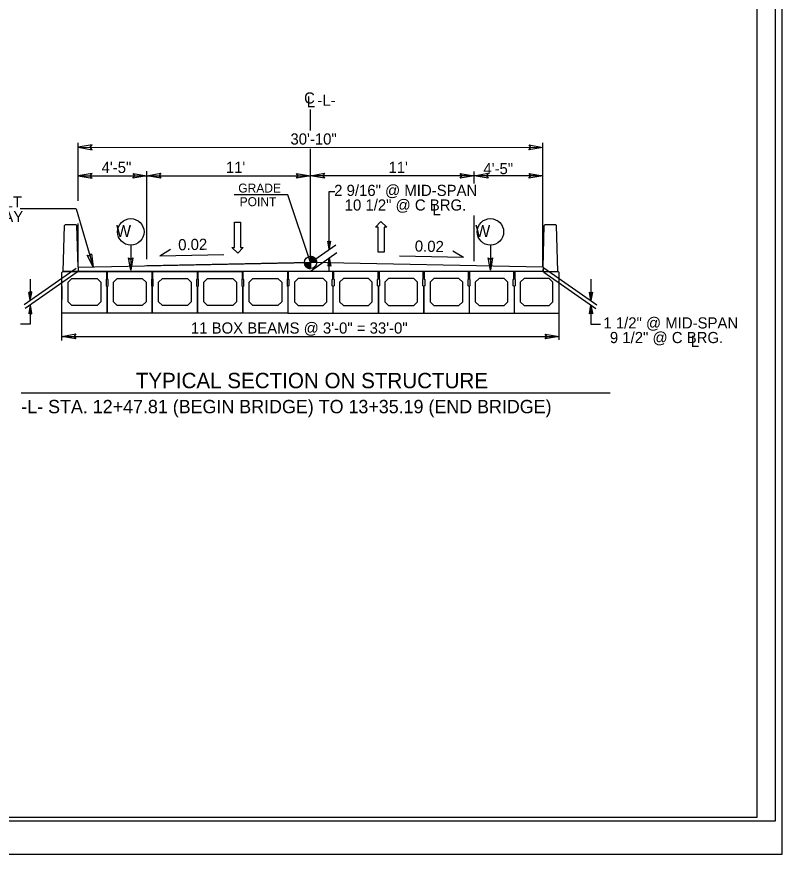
# Model space of a CAD drawing. Extents: x 573711 to 575883, y -54585 to -53485.
# Drawn here: x 574880 to 575395, y -54585 to -54021 of the extents above; entities that cross this region are included whole.
import ezdxf

# ---------------------------------------------------------------- set-up
doc = ezdxf.new("R2010")
doc.units = 0
for name, color, linetype in [('Old_Level_1', 7, 'Continuous'), ('Old_Level_11', 7, 'Continuous'), ('Old_Level_2', 7, 'Continuous'), ('Old_Level_20', 7, 'Continuous'), ('Old_Level_3', 7, 'Continuous'), ('Prop Dimension Text', 7, 'Continuous'), ('Prop Lane Arrow CELL', 7, 'Continuous'), ('Prop Terminator CELL', 7, 'Continuous'), ('Sheet Cutting Line CELL', 7, 'Continuous'), ('Sheet Plot Border Inside CELL', 7, 'Continuous'), ('Sheet Plot Border Outside CELL', 7, 'Continuous'), ('Sheet Typical CELL', 7, 'Continuous'), ('Typical Bridge Rail CELL', 7, 'Continuous'), ('Typical Terminator CELL', 7, 'Continuous')]:
    doc.layers.add(name, color=color, linetype=linetype)

msp = doc.modelspace()

# ---------------------------------------------------------------- linework, layer by layer
at = {"layer": 'Old_Level_1'}
for p, q in [((575077.4, -54097.63), (575077.41, -54083.4)), ((575077.4, -54186.4), (575077.4, -54109.84)), ((575090.02, -54177.56), (575090.02, -54138.73)), ((575090.02, -54138.73), (575093.85, -54138.73)), ((575077.4, -54186.4), (575094.41, -54174.48)), ((575090.02, -54177.56), (575089.05, -54172.03)), ((575089.05, -54172.03), (575090.02, -54172.75)), ((575089.19, -54172.14), (575090.02, -54177.56)), ((575090.02, -54177.56), (575089.32, -54172.24)), ((575089.46, -54172.35), (575090.02, -54177.56)), ((575090.02, -54177.56), (575089.6, -54172.44)), ((575089.74, -54172.54), (575090.02, -54177.56)), ((575090.02, -54177.56), (575089.88, -54172.64)), ((575090.02, -54177.56), (575091, -54172.03)), ((575090.02, -54172.75), (575091, -54172.03)), ((575090.02, -54177.56), (575090.85, -54172.14)), ((575090.71, -54172.24), (575090.02, -54177.56)), ((575090.02, -54177.56), (575090.57, -54172.35)), ((575090.44, -54172.44), (575090.02, -54177.56)), ((575090.02, -54177.56), (575090.3, -54172.54)), ((575090.16, -54172.64), (575090.02, -54177.56)), ((575090.02, -54172.75), (575090.02, -54177.56)), ((575077.39, -54192.18), (575095.11, -54179.77)), ((574920.85, -54189.55), (575077.4, -54186.4)), ((575077.4, -54186.4), (574967.2, -54188.62)), ((575073.25, -54186.4), (575077.4, -54186.4)), ((575077.39, -54190.55), (575077.4, -54186.4)), ((575077.4, -54186.4), (575077.39, -54190.55)), ((575077.4, -54186.4), (575077.4, -54182.25)), ((575233.96, -54189.55), (575077.4, -54186.4)), ((575081.54, -54186.4), (575077.4, -54186.4)), ((575090.02, -54183.34), (575089.05, -54188.86)), ((575090.02, -54183.34), (575089.19, -54188.76)), ((575089.33, -54188.65), (575090.02, -54183.34)), ((575090.02, -54183.34), (575089.46, -54188.55)), ((575089.6, -54188.45), (575090.02, -54183.34)), ((575090.02, -54183.34), (575089.74, -54188.35)), ((575089.88, -54188.25), (575090.02, -54183.34)), ((575090.02, -54183.34), (575091, -54188.86)), ((575090.85, -54188.76), (575090.02, -54183.34)), ((575090.02, -54183.34), (575090.71, -54188.65)), ((575090.58, -54188.55), (575090.02, -54183.34)), ((575090.02, -54183.34), (575090.44, -54188.45)), ((575090.3, -54188.35), (575090.02, -54183.34)), ((575090.02, -54183.34), (575090.16, -54188.25)), ((575090.02, -54188.14), (575090.02, -54183.34)), ((575090.02, -54192.62), (575090.02, -54183.34)), ((574919.63, -54190.4), (574884.61, -54214.93)), ((575090.02, -54188.14), (575089.05, -54188.86)), ((575091, -54188.86), (575090.02, -54188.14)), ((575234.59, -54189.97), (575270.23, -54214.94)), ((574920.25, -54192.97), (574885.21, -54217.51)), ((574888.59, -54197.7), (574888.59, -54212.13)), ((574920.94, -54192.56), (574910.79, -54192.56)), ((575233.99, -54192.56), (574920.84, -54192.56)), ((575233.89, -54192.56), (575244.26, -54192.56)), ((575234.58, -54192.98), (575269.63, -54217.52)), ((575266.24, -54197.7), (575266.24, -54212.14)), ((574888.59, -54212.13), (574887.62, -54206.61)), ((574887.62, -54206.61), (574888.59, -54207.33)), ((574887.76, -54206.71), (574888.59, -54212.13)), ((574888.59, -54212.13), (574889.57, -54206.61)), ((574888.59, -54207.33), (574889.57, -54206.61)), ((574888.59, -54212.13), (574888.87, -54207.12)), ((575266.24, -54212.14), (575265.27, -54206.61)), ((575266.24, -54207.33), (575265.27, -54206.61)), ((575266.24, -54212.14), (575265.96, -54207.12)), ((575266.24, -54212.14), (575267.22, -54206.61)), ((575267.22, -54206.61), (575266.24, -54207.33)), ((575267.07, -54206.71), (575266.24, -54212.14)), ((574888.59, -54215.15), (574887.61, -54220.68)), ((574888.59, -54219.96), (574887.61, -54220.68)), ((574888.59, -54215.15), (574888.59, -54228.07)), ((574888.59, -54215.15), (574889.56, -54220.68)), ((574889.56, -54220.68), (574888.59, -54219.96)), ((575266.25, -54215.15), (575265.27, -54220.68)), ((575265.27, -54220.68), (575266.25, -54219.96)), ((575266.25, -54215.15), (575266.25, -54228.07)), ((575266.25, -54215.15), (575267.22, -54220.68)), ((575266.25, -54219.96), (575267.22, -54220.68)), ((574888.59, -54228.07), (574882.15, -54228.07)), ((575266.25, -54228.07), (575272.68, -54228.07))]:
    msp.add_line(p, q, dxfattribs=at)
for points in [[(575073.27, -54186.4), (575073.27, -54186.85)], [(575073.35, -54186.4), (575073.35, -54187.34)], [(575073.43, -54186.4), (575073.43, -54187.64)], [(575073.51, -54186.4), (575073.51, -54187.89)], [(575073.6, -54186.4), (575073.6, -54188.08)], [(575073.68, -54186.4), (575073.68, -54188.25)], [(575073.76, -54186.4), (575073.76, -54188.41)], [(575073.85, -54186.4), (575073.85, -54188.56)], [(575073.93, -54186.4), (575073.93, -54188.69)], [(575074.01, -54186.4), (575074.01, -54188.81)], [(575074.1, -54186.4), (575074.1, -54188.92)], [(575074.18, -54186.4), (575074.18, -54189.02)], [(575074.26, -54186.4), (575074.26, -54189.12)], [(575074.34, -54186.4), (575074.34, -54189.21)], [(575074.43, -54186.4), (575074.43, -54189.3)], [(575074.51, -54186.4), (575074.51, -54189.39)], [(575074.59, -54186.4), (575074.59, -54189.46)], [(575074.68, -54186.4), (575074.68, -54189.54)], [(575074.76, -54186.4), (575074.76, -54189.61)], [(575074.84, -54186.4), (575074.84, -54189.67)], [(575074.93, -54186.4), (575074.93, -54189.74)], [(575075.01, -54186.4), (575075.01, -54189.79)], [(575075.09, -54186.4), (575075.09, -54189.85)], [(575075.17, -54186.4), (575075.17, -54189.9)], [(575075.26, -54186.4), (575075.26, -54189.96)], [(575075.34, -54186.4), (575075.34, -54190.01)], [(575075.42, -54186.4), (575075.42, -54190.05)], [(575075.51, -54186.4), (575075.51, -54190.1)], [(575075.59, -54186.4), (575075.59, -54190.13)], [(575075.67, -54186.4), (575075.67, -54190.17)], [(575075.76, -54186.4), (575075.76, -54190.21)], [(575075.84, -54186.4), (575075.84, -54190.25)], [(575075.92, -54186.4), (575075.92, -54190.28)], [(575076, -54186.4), (575076, -54190.31)], [(575076.09, -54186.4), (575076.09, -54190.34)], [(575076.17, -54186.4), (575076.17, -54190.36)], [(575076.25, -54186.4), (575076.25, -54190.38)], [(575076.34, -54186.4), (575076.34, -54190.41)], [(575076.42, -54186.4), (575076.42, -54190.43)], [(575076.5, -54186.4), (575076.5, -54190.45)], [(575076.58, -54186.4), (575076.58, -54190.47)], [(575076.67, -54186.4), (575076.67, -54190.49)], [(575076.75, -54186.4), (575076.75, -54190.49)], [(575076.83, -54186.4), (575076.83, -54190.51)], [(575076.92, -54186.4), (575076.92, -54190.52)], [(575077, -54186.4), (575077, -54190.53)], [(575077.08, -54186.4), (575077.08, -54190.54)], [(575077.17, -54186.4), (575077.16, -54190.54)], [(575077.25, -54186.4), (575077.25, -54190.55)], [(575077.33, -54186.4), (575077.33, -54190.55), (575077.33, -54190.55)], [(575077.43, -54182.25), (575077.43, -54182.25), (575077.43, -54186.4)], [(575077.52, -54182.25), (575077.52, -54186.4)], [(575077.6, -54182.26), (575077.6, -54186.4)], [(575077.68, -54182.26), (575077.68, -54186.4)], [(575077.76, -54182.27), (575077.76, -54186.4)], [(575077.85, -54182.28), (575077.85, -54186.4)], [(575077.93, -54182.29), (575077.93, -54186.4)], [(575078.01, -54182.3), (575078.01, -54186.4)], [(575078.1, -54182.31), (575078.1, -54186.4)], [(575078.18, -54182.33), (575078.18, -54186.4)], [(575078.26, -54182.35), (575078.26, -54186.4)], [(575078.35, -54182.36), (575078.35, -54186.4)], [(575078.43, -54182.38), (575078.43, -54186.4)], [(575078.51, -54182.41), (575078.51, -54186.4)], [(575078.59, -54182.43), (575078.59, -54186.4)], [(575078.68, -54182.46), (575078.68, -54186.4)], [(575078.76, -54182.48), (575078.76, -54186.4)], [(575078.84, -54182.51), (575078.84, -54186.4)], [(575078.93, -54182.55), (575078.93, -54186.4)], [(575079.01, -54182.59), (575079.01, -54186.4)], [(575079.09, -54182.62), (575079.09, -54186.4)], [(575079.17, -54182.66), (575079.17, -54186.4)], [(575079.26, -54182.7), (575079.26, -54186.4)], [(575079.34, -54182.74), (575079.34, -54186.4)], [(575079.42, -54182.79), (575079.42, -54186.4)], [(575079.51, -54182.83), (575079.51, -54186.4)], [(575079.59, -54182.88), (575079.59, -54186.4)], [(575079.67, -54182.94), (575079.67, -54186.4)], [(575079.76, -54182.99), (575079.76, -54186.4)], [(575079.84, -54183.06), (575079.84, -54186.4)], [(575079.92, -54183.11), (575079.92, -54186.4)], [(575080, -54183.18), (575080, -54186.4)], [(575080.09, -54183.25), (575080.09, -54186.4)], [(575080.17, -54183.32), (575080.17, -54186.4)], [(575080.25, -54183.4), (575080.25, -54186.4)], [(575080.34, -54183.48), (575080.34, -54186.4)], [(575080.42, -54183.56), (575080.42, -54186.4)], [(575080.5, -54183.66), (575080.5, -54186.4)], [(575080.58, -54183.76), (575080.58, -54186.4)], [(575080.67, -54183.86), (575080.67, -54186.4)], [(575080.75, -54183.97), (575080.75, -54186.4)], [(575080.83, -54184.09), (575080.83, -54186.4)], [(575080.92, -54184.22), (575080.92, -54186.4)], [(575081, -54184.36), (575081, -54186.4)], [(575081.08, -54184.5), (575081.08, -54186.4)], [(575081.17, -54184.68), (575081.17, -54186.4)], [(575081.25, -54184.87), (575081.25, -54186.4)], [(575081.33, -54185.1), (575081.33, -54186.4)], [(575081.41, -54185.39), (575081.41, -54186.4)], [(575081.5, -54185.81), (575081.5, -54186.4)]]:
    msp.add_lwpolyline(points, dxfattribs=at)
msp.add_circle((575077.39, -54186.4), 4.15, dxfattribs=at)
for start, end in [(179.9851, 269.9851), (359.9851, 89.9851)]:
    msp.add_arc((575077.39, -54186.4), 4.15, start, end, dxfattribs=at)
at = {"layer": 'Old_Level_11'}
for p, q in [((574920.84, -54145.02), (574920.84, -54105.85)), ((575233.96, -54189.55), (575233.97, -54105.85)), ((574920.84, -54108.85), (575233.97, -54108.88)), ((574920.84, -54128.02), (574967.2, -54128.03)), ((574967.2, -54184.19), (574967.2, -54125.03)), ((574967.2, -54184.19), (574967.2, -54125.03)), ((574967.2, -54184.19), (574967.2, -54126.35)), ((574967.2, -54128.03), (575077.4, -54128.04)), ((575187.6, -54128.05), (575077.4, -54128.04)), ((575187.6, -54133.14), (575187.6, -54125.05)), ((575233.97, -54128.05), (575187.6, -54128.05)), ((574919.53, -54150.36), (574881.91, -54150.36)), ((574919.53, -54150.36), (574930.97, -54189.34)), ((575187.59, -54185.62), (575187.6, -54154.69)), ((574920.85, -54189.55), (574920.84, -54160.13)), ((574920.85, -54189.55), (574920.85, -54169.38)), ((575233.99, -54189.55), (575233.99, -54169.38)), ((574956.33, -54174.74), (574956.33, -54191.59)), ((575198.53, -54174.74), (575198.53, -54191.59)), ((574909.95, -54239.06), (574909.95, -54211.95)), ((575244.9, -54238.55), (575244.9, -54211.44)), ((574909.95, -54236.23), (575244.9, -54236.26)), ((574882.58, -54274.25), (575279.13, -54274.29))]:
    msp.add_line(p, q, dxfattribs=at)
for points in [[(574929.92, -54180.59), (574930.97, -54189.34), (574926.99, -54181.42), (574928.79, -54182.04)], [(574957.75, -54183.34), (574956.33, -54191.59), (574954.86, -54183.29), (574956.33, -54184.35)], [(575199.96, -54183.34), (575198.53, -54191.59), (575197.07, -54183.29), (575198.53, -54184.35)]]:
    msp.add_lwpolyline(points, close=True, dxfattribs=at)
for centre in [(574956.33, -54165.83), (575198.54, -54165.83)]:
    msp.add_circle(centre, 8.91, dxfattribs=at)
at = {"layer": 'Old_Level_2'}
for p, q in [((574975.83, -54181.88), (574983.09, -54177.49)), ((574975.83, -54181.88), (575019.02, -54181.01)), ((575180.49, -54183.11), (575173.23, -54178.72)), ((575180.49, -54183.11), (575137.3, -54182.24))]:
    msp.add_line(p, q, dxfattribs=at)
at = {"layer": 'Old_Level_3'}
for p, q in [((575062.08, -54140.79), (575026.06, -54140.8)), ((575077.4, -54186.4), (575062.08, -54140.79))]:
    msp.add_line(p, q, dxfattribs=at)
at = {"layer": 'Prop Dimension Text'}
for p, q in [((575233.99, -54189.55), (575233.89, -54192.56)), ((575032.06, -54197.64), (575032.06, -54192.56)), ((575032.38, -54197.95), (575032.06, -54197.64)), ((575032.38, -54202.08), (575032.38, -54197.95)), ((575061.87, -54197.64), (575061.56, -54197.95)), ((575061.56, -54197.95), (575061.56, -54202.08)), ((575061.87, -54192.56), (575061.87, -54197.64)), ((575062.44, -54192.56), (575062.44, -54197.64)), ((575062.44, -54197.64), (575062.75, -54197.96)), ((575062.75, -54197.96), (575062.75, -54202.08)), ((575107.7, -54192.56), (575077.73, -54192.56)), ((575092.08, -54197.96), (575092.4, -54197.64)), ((575092.08, -54202.08), (575092.08, -54197.96)), ((575092.4, -54197.64), (575092.4, -54192.56)), ((575092.96, -54192.56), (575092.96, -54197.64)), ((575092.96, -54197.64), (575093.28, -54197.96)), ((575093.28, -54197.96), (575093.28, -54202.08)), ((575122.6, -54197.96), (575122.92, -54197.64)), ((575122.6, -54202.08), (575122.6, -54197.96)), ((575122.92, -54197.64), (575122.92, -54192.56)), ((575154, -54192.56), (575154, -54197.64)), ((575154, -54197.64), (575154.32, -54197.96)), ((575154.32, -54197.96), (575154.32, -54202.08)), ((575183.5, -54197.96), (575183.82, -54197.64)), ((575183.5, -54202.08), (575183.5, -54197.96)), ((575183.82, -54197.64), (575183.82, -54192.56)), ((575184.45, -54192.56), (575184.45, -54197.64)), ((575184.45, -54197.64), (575184.77, -54197.96)), ((575184.77, -54197.96), (575184.77, -54202.08)), ((575213.95, -54197.96), (575214.27, -54197.64)), ((575213.95, -54202.08), (575213.95, -54197.96)), ((575214.27, -54197.64), (575214.27, -54192.56)), ((575214.9, -54192.56), (575214.9, -54197.64)), ((575214.9, -54197.64), (575215.22, -54197.96)), ((575215.22, -54197.96), (575215.22, -54202.08)), ((575244.89, -54193.2), (575244.26, -54192.56)), ((575244.89, -54220.48), (575244.89, -54193.2)), ((574909.94, -54202.5), (574909.94, -54211.38)), ((575031.74, -54202.71), (575032.38, -54202.08)), ((575031.74, -54220.47), (575031.74, -54202.71)), ((575061.56, -54202.08), (575062.19, -54202.71)), ((575062.75, -54202.08), (575062.12, -54202.71)), ((575062.19, -54202.71), (575062.19, -54220.47)), ((575092.72, -54202.71), (575092.08, -54202.08)), ((575093.28, -54202.08), (575092.64, -54202.71)), ((575092.72, -54220.48), (575092.72, -54202.71)), ((575123.24, -54202.71), (575122.6, -54202.08)), ((575123.24, -54220.48), (575123.24, -54202.71)), ((575154.32, -54202.08), (575153.69, -54202.71)), ((575153.69, -54202.71), (575153.69, -54220.48)), ((575184.14, -54202.71), (575183.5, -54202.08)), ((575184.77, -54202.08), (575184.14, -54202.71)), ((575184.14, -54202.71), (575184.14, -54220.48)), ((575214.59, -54202.71), (575213.95, -54202.08)), ((575215.22, -54202.08), (575214.59, -54202.71)), ((575214.59, -54202.71), (575214.59, -54220.48)), ((575062.27, -54220.47), (575031.74, -54220.47)), ((575062.19, -54220.48), (575092.72, -54220.48)), ((575092.72, -54220.48), (575123.24, -54220.48)), ((575153.69, -54220.48), (575184.14, -54220.48)), ((575184.14, -54220.48), (575214.59, -54220.48)), ((575214.44, -54220.48), (575244.89, -54220.48))]:
    msp.add_line(p, q, dxfattribs=at)
for points in [[(574909.94, -54220.47), (574909.94, -54193.2), (574910.58, -54192.56), (574940.08, -54192.56), (574940.08, -54197.64), (574939.76, -54197.95), (574939.76, -54202.08), (574940.39, -54202.71), (574940.39, -54220.47)], [(574916.71, -54215.4), (574914.17, -54212.86), (574914.17, -54199.75), (574916.71, -54197.21), (574933.63, -54197.21), (574936.16, -54199.75), (574936.16, -54212.86), (574933.63, -54215.4)], [(574940.39, -54220.47), (574940.39, -54202.71), (574941.03, -54202.08), (574941.03, -54197.95), (574940.71, -54197.64), (574940.71, -54192.56), (574970.53, -54192.56), (574970.53, -54197.64), (574970.21, -54197.95), (574970.21, -54202.08), (574970.84, -54202.71), (574970.84, -54220.47)], [(574947.16, -54215.4), (574944.62, -54212.86), (574944.62, -54199.75), (574947.16, -54197.21), (574964.08, -54197.21), (574966.61, -54199.75), (574966.61, -54212.86), (574964.08, -54215.4)], [(574970.84, -54220.47), (574970.84, -54202.71), (574971.48, -54202.08), (574971.48, -54197.95), (574971.16, -54197.64), (574971.16, -54192.56), (575000.98, -54192.56), (575000.98, -54197.64), (575000.66, -54197.95), (575000.66, -54202.08), (575001.29, -54202.71), (575001.29, -54220.47)], [(574977.61, -54215.4), (574975.07, -54212.86), (574975.07, -54199.75), (574977.61, -54197.21), (574994.53, -54197.21), (574997.06, -54199.75), (574997.06, -54212.86), (574994.53, -54215.4)], [(575001.29, -54220.47), (575001.29, -54202.71), (575001.93, -54202.08), (575001.93, -54197.95), (575001.61, -54197.64), (575001.61, -54192.56), (575031.43, -54192.56), (575031.43, -54197.64), (575031.11, -54197.95), (575031.11, -54202.08), (575031.74, -54202.71), (575031.74, -54220.47)], [(575008.06, -54215.4), (575005.52, -54212.86), (575005.52, -54199.75), (575008.06, -54197.21), (575024.98, -54197.21), (575027.51, -54199.75), (575027.51, -54212.86), (575024.98, -54215.4)], [(575038.51, -54215.4), (575035.97, -54212.86), (575035.97, -54199.75), (575038.51, -54197.21), (575055.43, -54197.21), (575057.96, -54199.75), (575057.96, -54212.86), (575055.43, -54215.4)], [(575085.95, -54215.4), (575088.49, -54212.86), (575088.49, -54199.75), (575085.95, -54197.22), (575069.03, -54197.22), (575066.49, -54199.75), (575066.49, -54212.86), (575069.03, -54215.4)], [(575116.47, -54215.4), (575119.01, -54212.86), (575119.01, -54199.75), (575116.47, -54197.22), (575099.55, -54197.22), (575097.02, -54199.75), (575097.02, -54212.86), (575099.55, -54215.4)], [(575153.69, -54220.48), (575153.69, -54202.71), (575153.05, -54202.08), (575153.05, -54197.96), (575153.37, -54197.64), (575153.37, -54192.56), (575123.56, -54192.56), (575123.56, -54197.64), (575123.87, -54197.96), (575123.87, -54202.08), (575123.24, -54202.71), (575123.24, -54220.48)], [(575146.92, -54215.4), (575149.46, -54212.86), (575149.46, -54199.75), (575146.92, -54197.22), (575130, -54197.22), (575127.47, -54199.75), (575127.47, -54212.86), (575130, -54215.4)], [(575177.37, -54215.4), (575179.91, -54212.86), (575179.91, -54199.75), (575177.37, -54197.22), (575160.45, -54197.22), (575157.92, -54199.75), (575157.92, -54212.86), (575160.45, -54215.4)], [(575207.82, -54215.4), (575210.36, -54212.86), (575210.36, -54199.75), (575207.82, -54197.22), (575190.9, -54197.22), (575188.37, -54199.75), (575188.37, -54212.86), (575190.9, -54215.4)], [(575238.12, -54215.4), (575240.66, -54212.86), (575240.66, -54199.75), (575238.12, -54197.22), (575221.21, -54197.22), (575218.67, -54199.75), (575218.67, -54212.86), (575221.21, -54215.4)]]:
    msp.add_lwpolyline(points, close=True, dxfattribs=at)
at = {"layer": 'Prop Lane Arrow CELL'}
for p, q in [((575026.28, -54176.28), (575026.28, -54159.27)), ((575026.28, -54159.27), (575030.29, -54159.27)), ((575030.29, -54159.27), (575030.29, -54176.28)), ((575121.09, -54162.54), (575124.85, -54158.72)), ((575122.91, -54162.54), (575121.09, -54162.54)), ((575122.91, -54179.55), (575122.91, -54162.54)), ((575124.85, -54158.72), (575128.74, -54162.54)), ((575128.74, -54162.54), (575126.92, -54162.54)), ((575126.92, -54162.54), (575126.92, -54179.55)), ((575028.34, -54180.11), (575024.45, -54176.28)), ((575024.45, -54176.28), (575026.28, -54176.28)), ((575032.11, -54176.28), (575028.34, -54180.11)), ((575030.29, -54176.28), (575032.11, -54176.28)), ((575126.92, -54179.55), (575122.91, -54179.55))]:
    msp.add_line(p, q, dxfattribs=at)
at = {"layer": 'Prop Terminator CELL'}
for points in [[(574887.6, -54206.35), (574888.59, -54212.13), (574889.62, -54206.31), (574888.59, -54207.05)], [(575267.24, -54206.35), (575266.24, -54212.14), (575265.21, -54206.32), (575266.24, -54207.06)], [(574889.58, -54220.94), (574888.59, -54215.15), (574887.56, -54220.97), (574888.59, -54220.23)], [(575265.25, -54220.94), (575266.25, -54215.15), (575267.28, -54220.97), (575266.25, -54220.23)]]:
    msp.add_lwpolyline(points, close=True, dxfattribs=at)
at = {"layer": 'Sheet Cutting Line CELL'}
msp.add_line((573711.13, -54585.01), (575395.13, -54585.01), dxfattribs=at)
at = {"layer": 'Sheet Plot Border Inside CELL'}
msp.add_lwpolyline([(575390.63, -53507.46), (573724.13, -53507.46), (573724.13, -54562.56), (575390.63, -54562.56)], close=True, dxfattribs=at)
at = {"layer": 'Sheet Plot Border Outside CELL'}
msp.add_lwpolyline([(575395.13, -53485.01), (573711.13, -53485.01), (573711.13, -54585.01), (575395.13, -54585.01)], close=True, dxfattribs=at)
at = {"layer": 'Sheet Typical CELL'}
msp.add_lwpolyline([(575378.13, -53510.01), (573878.13, -53510.01), (573878.13, -54560.01), (575378.13, -54560.01)], close=True, dxfattribs=at)
at = {"layer": 'Typical Bridge Rail CELL'}
for p, q in [((574910.79, -54192.56), (574911.76, -54161.46)), ((574911.76, -54161.46), (574912.42, -54160.82)), ((574912.42, -54160.82), (574919.31, -54160.82)), ((574919.97, -54161.46), (574919.31, -54160.82)), ((574920.85, -54189.55), (574919.97, -54161.46)), ((575233.99, -54189.55), (575234.87, -54161.46)), ((575234.87, -54161.46), (575235.52, -54160.83)), ((575235.52, -54160.83), (575242.42, -54160.83)), ((575243.07, -54161.46), (575242.42, -54160.83)), ((575244.04, -54192.56), (575243.07, -54161.46)), ((574920.85, -54189.55), (574920.94, -54192.56)), ((574920.85, -54189.55), (574920.85, -54192.56)), ((575233.99, -54189.55), (575233.99, -54192.56))]:
    msp.add_line(p, q, dxfattribs=at)
at = {"layer": 'Typical Terminator CELL'}
for points in [[(574930.21, -54107.24), (574920.84, -54108.85), (574930.26, -54110.52), (574929.07, -54108.85)], [(575224.59, -54107.27), (575233.97, -54108.88), (575224.54, -54110.55), (575225.74, -54108.88)], [(574930.21, -54126.41), (574920.84, -54128.02), (574930.27, -54129.69), (574929.07, -54128.02)], [(574957.83, -54126.41), (574967.2, -54128.03), (574957.78, -54129.69), (574958.98, -54128.03)], [(574976.58, -54129.64), (574967.2, -54128.03), (574976.63, -54126.36), (574975.43, -54128.03)], [(575068.03, -54126.42), (575077.4, -54128.04), (575067.98, -54129.7), (575069.17, -54128.04)], [(575086.77, -54129.65), (575077.4, -54128.04), (575086.83, -54126.37), (575085.63, -54128.04)], [(575178.23, -54126.43), (575187.6, -54128.05), (575178.17, -54129.71), (575179.37, -54128.05)], [(575196.97, -54129.66), (575187.6, -54128.05), (575197.02, -54126.38), (575195.83, -54128.05)], [(575224.59, -54126.44), (575233.97, -54128.05), (575224.54, -54129.72), (575225.74, -54128.05)], [(574919.32, -54237.84), (574909.95, -54236.23), (574919.38, -54234.56), (574918.18, -54236.23)], [(575235.52, -54234.65), (575244.9, -54236.26), (575235.47, -54237.93), (575236.67, -54236.26)]]:
    msp.add_lwpolyline(points, close=True, dxfattribs=at)

# ---------------------------------------------------------------- texts
at = {"layer": 'Old_Level_1'}
for s, height, p in [('2 9/16" @ MID-SPAN', 7.513, (575093.32, -54141.62)), ('10 1/2" @ C BRG.', 7.513, (575100.4, -54151.47)), ('L', 7.51, (575159.49, -54154.68)), ('1 1/2" @ MID-SPAN', 7.513, (575274.65, -54230.89)), ('9 1/2" @ C BRG.', 7.513, (575279.04, -54240.74)), ('L', 7.51, (575333.54, -54243.27)), ('-L- STA. 12+47.81 (BEGIN BRIDGE) TO 13+35.19 (END BRIDGE)', 9, (574882.58, -54287.99))]:
    msp.add_text(s, height=height, dxfattribs=at).set_placement(p)
at = {"layer": 'Old_Level_11'}
for s, height, rotation, p in [('C', 7.51, 359.9946, (575073.05, -54079.39)), ('-L-', 7.513, 359.9946, (575082.06, -54080.89)), ('L', 7.51, 359.9415, (575074.92, -54081.92)), ('30\'-10"', 7.513, 359.9946, (575063.86, -54107)), ('4\'-5"', 7.513, 359.9946, (574936.66, -54126.15)), ("11'", 7.513, 359.9946, (575020.33, -54126.11)), ("11'", 7.513, 359.9946, (575129.89, -54126.12)), ('4\'-5"', 7.513, 359.9946, (575193.84, -54126.94)), ('ASPHALT', 7.513, 359.9946, (574837.25, -54149.38)), ('OVERLAY', 7.513, 359.9946, (574836.42, -54159.23)), ('11 BOX BEAMS @ 3\'-0" = 33\'-0"', 7.513, 359.9946, (574996.82, -54234.31))]:
    msp.add_text(s, height=height, rotation=rotation, dxfattribs=at).set_placement(p)
at = {"layer": 'Old_Level_20'}
for p in [(574943.46, -54169.23), (575185.4, -54169.23)]:
    msp.add_text(' W', height=7.977, dxfattribs=at).set_placement(p)
at = {"layer": 'Old_Level_3'}
for s, height, rotation, p in [('GRADE', 6.046, 0.0054, (575028.73, -54139.35)), ('POINT', 6.046, 0.0054, (575029.66, -54148.51)), ('0.02', 7.513, 1.1511, (574988.33, -54178.26)), ('0.02', 7.513, 358.8489, (575147.57, -54179.08)), ('TYPICAL SECTION ON STRUCTURE', 10.3693, 359.9946, (574959.69, -54271.12))]:
    msp.add_text(s, height=height, rotation=rotation, dxfattribs=at).set_placement(p)

doc.saveas('drawing.dxf')
